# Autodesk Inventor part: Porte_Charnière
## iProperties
Created: 2009-01
Part Number: Porte_Charnière
Document SubType Name: Modeling
Designer: claivier
Author: claivier
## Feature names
1. Extrusion1
2. Extrusion2
3. Réseau rectangulaire1 [Rectangular Pattern]
4. Perçage2 [Hole]
